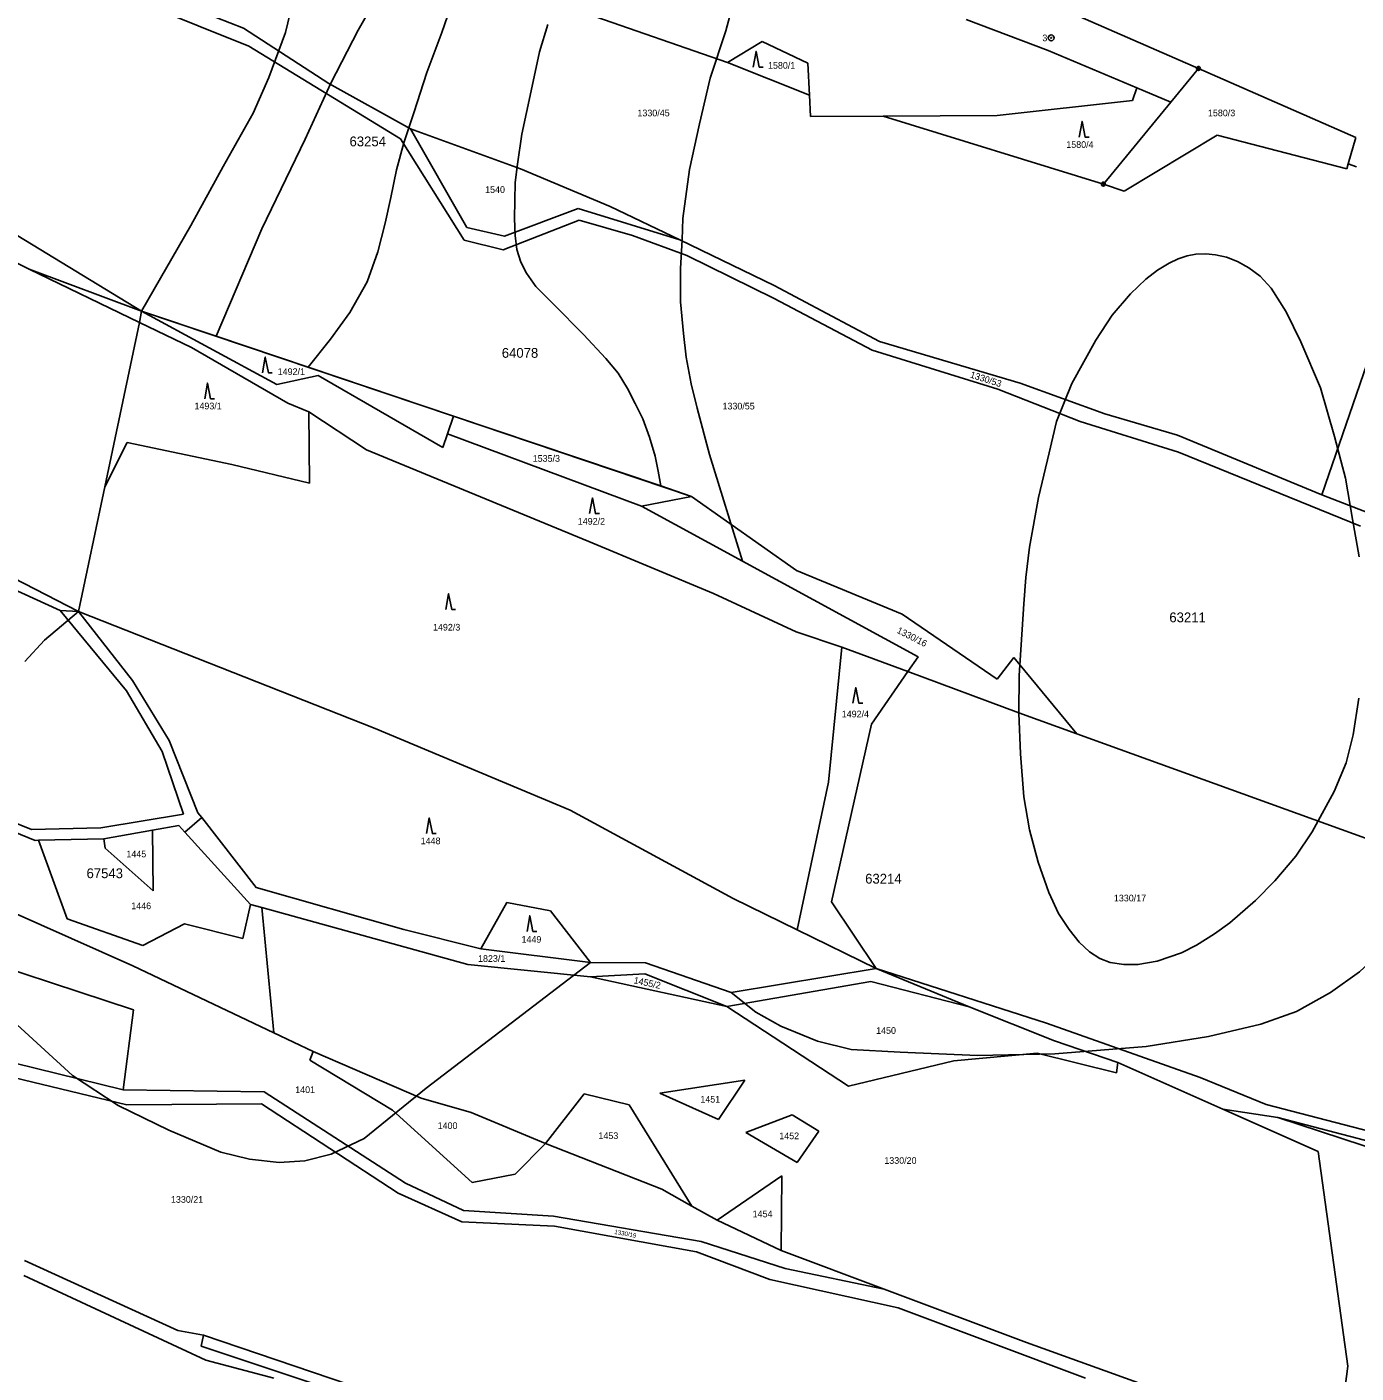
# Model space of a CAD drawing. Extents: x -546762 to -540209, y -1046851 to -1035694.
# Drawn here: x -542968.6 to -542629.5, y -1041335.5 to -1040992 of the extents above; entities that cross this region are included whole.
import ezdxf

# ---------------------------------------------------------------- set-up
doc = ezdxf.new("R2010")
doc.units = 0
for name, color, linetype in [('Vrstva 1', 7, 'Continuous'), ('Vrstva 17', 7, 'Continuous'), ('Vrstva 18', 7, 'Continuous'), ('Vrstva 24', 7, 'Continuous'), ('Vrstva 25', 7, 'Continuous'), ('Vrstva 52', 7, 'Continuous'), ('Vrstva 53', 7, 'Continuous'), ('Vrstva 6', 7, 'Continuous')]:
    doc.layers.add(name, color=color, linetype=linetype)

msp = doc.modelspace()

# ---------------------------------------------------------------- linework, layer by layer
at = {"layer": 'Vrstva 1'}
for points in [[(-542669.69, -1041002.63), (-542786.34, -1040951.58)], [(-542825.69, -1040988.7), (-542789.86, -1041001.15)], [(-542789.86, -1041001.15), (-542768.95, -1041009.45)], [(-542676.76, -1041011.23), (-542669.69, -1041002.63)], [(-542629.49, -1041020.22), (-542669.69, -1041002.63)], [(-542768.95, -1041009.45), (-542768.67, -1041014.93)], [(-542693.95, -1041032.14), (-542676.76, -1041011.23)], [(-542768.67, -1041014.93), (-542750.14, -1041014.82)], [(-542693.95, -1041032.14), (-542750.14, -1041014.82)], [(-542688.6, -1041033.92), (-542664.92, -1041019.69)], [(-542664.92, -1041019.69), (-542631.83, -1041028.25)], [(-542629.49, -1041020.22), (-542631.46, -1041026.99)], [(-542631.46, -1041026.99), (-542631.83, -1041028.25)], [(-542693.95, -1041032.14), (-542688.6, -1041033.92)], [(-542939.35, -1041064.58), (-542968.01, -1041053.85)], [(-542968.01, -1041053.85), (-542939.89, -1041067.45)], [(-542859.72, -1041091.39), (-542939.35, -1041064.58)], [(-542939.89, -1041067.45), (-542948.74, -1041109.37)], [(-542861.28, -1041095.86), (-542859.72, -1041091.39)], [(-542798.99, -1041111.82), (-542859.72, -1041091.39)], [(-542811.78, -1041114.34), (-542861.28, -1041095.86)], [(-542948.74, -1041109.37), (-542955.45, -1041141.18)], [(-542811.78, -1041114.34), (-542798.99, -1041111.82)], [(-542741.2, -1041152.77), (-542811.78, -1041114.34)], [(-542955.45, -1041141.18), (-542941.68, -1041158.79)], [(-542743.82, -1041156.54), (-542741.2, -1041152.77)], [(-542753.11, -1041169.93), (-542743.82, -1041156.54)], [(-542932.33, -1041174.09), (-542941.68, -1041158.79)], [(-542753.11, -1041169.93), (-542763.35, -1041215.27)], [(-542924.99, -1041192.52), (-542932.33, -1041174.09)], [(-542924.99, -1041192.52), (-542924, -1041193.79)], [(-542924, -1041193.79), (-542928.32, -1041197.49)], [(-542924, -1041193.79), (-542910.14, -1041211.61)], [(-542928.32, -1041197.49), (-542911.54, -1041215.94)], [(-542910.14, -1041211.61), (-542872.43, -1041222.33)], [(-542908.66, -1041216.74), (-542911.54, -1041215.94)], [(-542751.91, -1041232.29), (-542763.35, -1041215.27)], [(-542856.12, -1041231.25), (-542908.66, -1041216.74)], [(-542872.43, -1041222.33), (-542852.79, -1041227.26)], [(-542852.79, -1041227.26), (-542824.82, -1041230.74)], [(-542856.12, -1041231.25), (-542824.77, -1041234.42)], [(-542824.82, -1041230.74), (-542810.78, -1041230.84)], [(-542824.77, -1041234.42), (-542810.97, -1041233.64)], [(-542810.97, -1041233.64), (-542790.04, -1041241.95)], [(-542810.78, -1041230.84), (-542788.89, -1041238.38)], [(-542788.89, -1041238.38), (-542751.91, -1041232.29)], [(-542751.91, -1041232.29), (-542728.18, -1041242.08)], [(-542790.04, -1041241.95), (-542824.77, -1041234.42)], [(-542753.24, -1041235.61), (-542790.04, -1041241.95)], [(-542753.24, -1041235.61), (-542728.18, -1041242.08)]]:
    msp.add_lwpolyline(points, dxfattribs=at)
at = {"layer": 'Vrstva 24'}
for centre, radius in [((-542707.25, -1040994.84), 0.75), ((-542707.25, -1040994.84), 0.1), ((-542669.69, -1041002.63), 0.5), ((-542669.69, -1041002.63), 0.1), ((-542693.95, -1041032.14), 0.5), ((-542693.95, -1041032.14), 0.1)]:
    msp.add_circle(centre, radius, dxfattribs=at)
at = {"layer": 'Vrstva 25'}
for points in [[(-542783.26, -1041002.29), (-542782.56, -1040998.29), (-542781.76, -1041002.29), (-542780.76, -1041002.29)], [(-542700.09, -1041020.15), (-542699.39, -1041016.15), (-542698.59, -1041020.15), (-542697.59, -1041020.15)], [(-542908.49, -1041080.27), (-542907.79, -1041076.27), (-542906.99, -1041080.27), (-542905.99, -1041080.27)], [(-542923.22, -1041086.91), (-542922.52, -1041082.91), (-542921.72, -1041086.91), (-542920.72, -1041086.91)], [(-542825.03, -1041116.21), (-542824.33, -1041112.21), (-542823.53, -1041116.21), (-542822.53, -1041116.21)], [(-542861.72, -1041140.66), (-542861.02, -1041136.66), (-542860.22, -1041140.66), (-542859.22, -1041140.66)], [(-542757.83, -1041164.61), (-542757.13, -1041160.61), (-542756.33, -1041164.61), (-542755.33, -1041164.61)], [(-542866.65, -1041197.87), (-542865.95, -1041193.87), (-542865.15, -1041197.87), (-542864.15, -1041197.87)], [(-542840.98, -1041222.83), (-542840.28, -1041218.83), (-542839.48, -1041222.83), (-542838.48, -1041222.83)]]:
    msp.add_lwpolyline(points, dxfattribs=at)
at = {"layer": 'Vrstva 52'}
for points in [[(-542920.34, -1041070.98), (-542908.65, -1041043.54), (-542897.63, -1041020.64), (-542891.06, -1041006.43), (-542884.06, -1040992.86), (-542874.53, -1040976.11), (-542869.86, -1040965.72), (-542867.09, -1040958.26), (-542863.49, -1040946.59), (-542859.89, -1040933.45), (-542856.29, -1040921.99), (-542853.11, -1040913.94), (-542850.14, -1040907.58), (-542845.99, -1040901.52), (-542840.91, -1040895.34), (-542835.58, -1040889.88), (-542829.76, -1040884.43), (-542823.95, -1040879.71), (-542817.53, -1040875.71), (-542811.72, -1040873.16), (-542804.94, -1040871.59), (-542798.88, -1040870.86), (-542792.34, -1040870.98)], [(-542939.35, -1041064.58), (-542926.79, -1041042.67), (-542918.53, -1041027.62), (-542910.9, -1041014.05), (-542906.87, -1041004.93), (-542902.63, -1040993.48), (-542899.45, -1040980.33)], [(-542896.85, -1041078.89), (-542891.1, -1041071.73), (-542886.22, -1041064.94), (-542881.77, -1041057.1), (-542879.02, -1041049.46), (-542877.23, -1041042.07), (-542875.78, -1041035.52), (-542874.33, -1041028.49), (-542872.39, -1041021.59), (-542869.84, -1041013.95), (-542866.57, -1041003.65), (-542862.7, -1040993.48), (-542859.07, -1040982.81)], [(-542787.68, -1040983.46), (-542790.25, -1040993.01), (-542794.28, -1041005.1), (-542797.03, -1041016.76), (-542799.58, -1041028.42), (-542801.27, -1041040.93), (-542801.44, -1041046.4), (-542801.8, -1041053.67), (-542801.8, -1041062.16), (-542801.08, -1041070.28), (-542800.35, -1041076.33), (-542799.14, -1041083.12), (-542797.57, -1041089.3), (-542794.42, -1041101.17), (-542786.05, -1041128.35)], [(-542835.66, -1040991.42), (-542837.81, -1040998.42), (-542839.95, -1041008.32), (-542842.31, -1041019.4), (-542843.41, -1041027.08), (-542844.04, -1041031.72), (-542844.17, -1041040.93), (-542844.04, -1041045.22), (-542843.57, -1041048.85), (-542842.6, -1041052.03), (-542841.15, -1041054.87), (-542838.73, -1041058.26), (-542834.16, -1041062.9), (-542826.55, -1041070.52), (-542820.87, -1041076.61), (-542817.76, -1041080.42), (-542815.34, -1041084.3), (-542813.38, -1041088.09), (-542811.44, -1041092.03), (-542809.78, -1041096.67), (-542808.26, -1041101.52), (-542807.56, -1041105.4), (-542806.89, -1041109.16)], [(-543046.13, -1041004.38), (-543041.77, -1041005.42), (-543036.64, -1041007.64), (-543023.7, -1041013.66), (-543011.94, -1041020.45), (-542939.35, -1041064.58)], [(-542628.77, -1041163.32), (-542630.22, -1041172.65), (-542632.04, -1041179.8), (-542635.1, -1041187.1), (-542640.64, -1041197.42), (-542644.86, -1041203.58), (-542650.19, -1041209.95), (-542655.17, -1041214.94), (-542661.67, -1041220.61), (-542665.62, -1041223.45), (-542670.19, -1041226.29), (-542673.99, -1041228.3), (-542680.22, -1041230.45), (-542685.13, -1041231.28), (-542688.73, -1041231.28), (-542692.19, -1041230.72), (-542694.82, -1041229.75), (-542697.45, -1041228.02), (-542700.15, -1041225.53), (-542702.71, -1041222.34), (-542705.36, -1041218.26), (-542707.9, -1041212.93), (-542710.57, -1041205.17), (-542712.75, -1041196.93), (-542714.2, -1041188.45), (-542715.05, -1041177.54), (-542715.53, -1041167.12), (-542715.41, -1041157.55), (-542714.2, -1041139.25), (-542713.73, -1041132.49), (-542712.76, -1041124.74), (-542710.46, -1041112.14), (-542707.79, -1041100.75), (-542705.88, -1041092.71), (-542702.01, -1041083.02), (-542695.91, -1041071.99), (-542691.72, -1041065.58), (-542687.01, -1041060.16), (-542683.11, -1041056.39), (-542680.1, -1041054.06), (-542677.13, -1041052.28), (-542674.88, -1041051.25), (-542672.59, -1041050.46), (-542670.37, -1041049.98)], [(-542670.37, -1041049.98), (-542667.76, -1041049.94), (-542665.31, -1041050.18)], [(-542665.31, -1041050.18), (-542662.5, -1041050.77), (-542659.73, -1041051.88), (-542656.85, -1041053.54), (-542653.96, -1041055.6), (-542651.17, -1041058.71), (-542647.29, -1041064.77), (-542643.54, -1041072.41), (-542638.57, -1041084.16), (-542634.95, -1041096.55), (-542632.16, -1041107.21), (-542630.35, -1041117.63), (-542628.65, -1041127.21)], [(-542955.45, -1041141.18), (-542948.74, -1041109.37), (-542939.89, -1041067.45), (-542939.35, -1041064.58)], [(-542939.35, -1041064.58), (-542920.34, -1041070.98)], [(-542920.34, -1041070.98), (-542896.85, -1041078.89)], [(-542896.85, -1041078.89), (-542859.72, -1041091.39), (-542806.89, -1041109.16)], [(-542806.89, -1041109.16), (-542798.99, -1041111.82), (-542811.78, -1041114.34), (-542786.05, -1041128.35)], [(-542786.05, -1041128.35), (-542741.2, -1041152.77), (-542743.82, -1041156.54), (-542753.11, -1041169.93), (-542763.35, -1041215.27), (-542751.91, -1041232.29), (-542788.89, -1041238.38)], [(-542969.1, -1041153.99), (-542964.14, -1041148.54), (-542955.45, -1041141.18)], [(-542955.45, -1041141.18), (-542941.68, -1041158.79)], [(-542941.68, -1041158.79), (-542932.33, -1041174.09), (-542924.99, -1041192.52), (-542924, -1041193.79), (-542910.14, -1041211.61), (-542872.43, -1041222.33), (-542852.79, -1041227.26), (-542824.82, -1041230.74)], [(-542788.89, -1041238.38), (-542782.63, -1041243.39), (-542776.22, -1041247.02), (-542766.89, -1041250.78), (-542758.29, -1041252.96), (-542745.79, -1041253.66), (-542726.08, -1041254.5), (-542706.37, -1041254.08), (-542683.05, -1041252.17), (-542667.16, -1041249.63), (-542653.81, -1041246.45), (-542644.69, -1041243.26), (-542636, -1041238.39), (-542628.59, -1041233.09), (-542620.74, -1041225.88), (-542615.37, -1041218.81), (-542605.62, -1041201.21)], [(-542824.82, -1041230.74), (-542866.71, -1041262.8), (-542882.57, -1041275.65), (-542890.93, -1041279.65), (-542897.71, -1041281.34), (-542904.25, -1041281.77), (-542911.76, -1041280.92), (-542919.15, -1041279.1), (-542932.35, -1041273.53), (-542945.31, -1041267.23), (-542956.93, -1041259.59), (-542974.13, -1041243.84)], [(-542788.89, -1041238.38), (-542810.78, -1041230.84), (-542824.82, -1041230.74)]]:
    msp.add_lwpolyline(points, dxfattribs=at)
at = {"layer": 'Vrstva 6'}
for points in [[(-542962.12, -1040973.22), (-542913.3, -1040992.35)], [(-542963.29, -1040976.25), (-542911.96, -1040996.99)], [(-542913.3, -1040992.35), (-542891.53, -1041006.49)], [(-542708.03, -1040998.09), (-542728.96, -1040990.15)], [(-542781, -1040995.72), (-542789.86, -1041001.15)], [(-542769.37, -1041001.31), (-542781, -1040995.72)], [(-542911.96, -1040996.99), (-542873.27, -1041020.63)], [(-542685.4, -1041007.6), (-542708.03, -1040998.09)], [(-542768.95, -1041009.45), (-542769.37, -1041001.31)], [(-542891.53, -1041006.49), (-542870.7, -1041018.06)], [(-542686.51, -1041010.8), (-542685.4, -1041007.6)], [(-542676.76, -1041011.23), (-542685.4, -1041007.6)], [(-542721.02, -1041014.65), (-542686.51, -1041010.8)], [(-542750.14, -1041014.82), (-542721.02, -1041014.65)], [(-542873.27, -1041020.63), (-542857.04, -1041046.49)], [(-542870.7, -1041018.06), (-542842.69, -1041028.25)], [(-542856.36, -1041043.2), (-542870.7, -1041018.06)], [(-542631.46, -1041026.99), (-542629.39, -1041027.77)], [(-542842.69, -1041028.25), (-542819.75, -1041037.82)], [(-542638.23, -1041111.45), (-542611.71, -1041034.4)], [(-542968.01, -1041053.85), (-543006.53, -1041034.56)], [(-542819.75, -1041037.82), (-542801.98, -1041046.4)], [(-542847.04, -1041048.92), (-542827.72, -1041041.33)], [(-542846.72, -1041045.45), (-542827.96, -1041038.38)], [(-542827.96, -1041038.38), (-542801.98, -1041046.4)], [(-542827.72, -1041041.33), (-542814.08, -1041045.23)], [(-542856.36, -1041043.2), (-542846.72, -1041045.45)], [(-542857.04, -1041046.49), (-542847.04, -1041048.92)], [(-542814.08, -1041045.23), (-542800.19, -1041050.39)], [(-542801.98, -1041046.4), (-542777.97, -1041058)], [(-542800.19, -1041050.39), (-542777.96, -1041061.32)], [(-542777.97, -1041058), (-542751.07, -1041072.3)], [(-542777.96, -1041061.32), (-542752.92, -1041074.51)], [(-542904.79, -1041083.3), (-542939.35, -1041064.58)], [(-542939.89, -1041067.45), (-542926.62, -1041073.87)], [(-542751.07, -1041072.3), (-542715.17, -1041082.9)], [(-542926.62, -1041073.87), (-542902.06, -1041088.06)], [(-542752.92, -1041074.51), (-542720.9, -1041084.45)], [(-542894.24, -1041080.96), (-542904.79, -1041083.3)], [(-542862.49, -1041099.32), (-542894.24, -1041080.96)], [(-542720.9, -1041084.45), (-542699.9, -1041092.71)], [(-542715.17, -1041082.9), (-542693.54, -1041090.8)], [(-542902.06, -1041088.06), (-542896.69, -1041090.28)], [(-542896.5, -1041108.47), (-542896.69, -1041090.28)], [(-542896.69, -1041090.28), (-542881.91, -1041099.92)], [(-542699.9, -1041092.71), (-542674.77, -1041100.51)], [(-542693.54, -1041090.8), (-542675.04, -1041096.2)], [(-542861.28, -1041095.86), (-542862.49, -1041099.32)], [(-542675.04, -1041096.2), (-542638.23, -1041111.45)], [(-542948.74, -1041109.37), (-542943.05, -1041098.05)], [(-542943.05, -1041098.05), (-542916.32, -1041103.69)], [(-542881.91, -1041099.92), (-542825.25, -1041123.35)], [(-542674.77, -1041100.51), (-542628.37, -1041119.45)], [(-542916.32, -1041103.69), (-542896.5, -1041108.47)], [(-543023.47, -1041112.01), (-542960.13, -1041140.93)], [(-542798.99, -1041111.82), (-542772.23, -1041130.77)], [(-542638.23, -1041111.45), (-542545.5, -1041147.28)], [(-542825.25, -1041123.35), (-542793.41, -1041136.64)], [(-542980.42, -1041128.34), (-542955.45, -1041141.18)], [(-542772.23, -1041130.77), (-542745.27, -1041141.86)], [(-542772.36, -1041146.4), (-542793.41, -1041136.64)], [(-542955.45, -1041141.18), (-542960.13, -1041140.93)], [(-542960.13, -1041140.93), (-542943.22, -1041161.44)], [(-542955.45, -1041141.18), (-542879.75, -1041171.07)], [(-542745.27, -1041141.86), (-542721.07, -1041158.46)], [(-542760.71, -1041150.26), (-542772.36, -1041146.4)], [(-542760.71, -1041150.26), (-542764.09, -1041184.74)], [(-542743.82, -1041156.54), (-542760.71, -1041150.26)], [(-542716.81, -1041152.94), (-542721.07, -1041158.46)], [(-542700.7, -1041172.43), (-542716.81, -1041152.94)], [(-542715.53, -1041167.07), (-542743.82, -1041156.54)], [(-542943.22, -1041161.44), (-542934.1, -1041176.87)], [(-542700.7, -1041172.43), (-542715.53, -1041167.07)], [(-542967.46, -1041196.84), (-543032.07, -1041170.61)], [(-542879.75, -1041171.07), (-542829.99, -1041191.92)], [(-542597.92, -1041209.59), (-542700.7, -1041172.43)], [(-542934.1, -1041176.87), (-542928.61, -1041192.88)], [(-542764.09, -1041184.74), (-542772.06, -1041222.43)], [(-542984.39, -1041192.33), (-542966.48, -1041199.59)], [(-542788.43, -1041214.43), (-542829.99, -1041191.92)], [(-542928.61, -1041192.88), (-542949.73, -1041196.39)], [(-542929.83, -1041195.83), (-542936.54, -1041197.01)], [(-542929.83, -1041195.83), (-542928.32, -1041197.49)], [(-542949.73, -1041196.39), (-542967.46, -1041196.84)], [(-542948.93, -1041199.19), (-542965.65, -1041199.57)], [(-542936.54, -1041197.01), (-542948.93, -1041199.19)], [(-542948.93, -1041199.19), (-542948.64, -1041201.55)], [(-542936.54, -1041197.01), (-542936.39, -1041212.47)], [(-542965.65, -1041199.57), (-542966.48, -1041199.59)], [(-542958.35, -1041219.58), (-542965.65, -1041199.57)], [(-542948.64, -1041201.55), (-542936.39, -1041212.47)], [(-543004.26, -1041203.7), (-542941.53, -1041231.62)], [(-542913.47, -1041224.64), (-542911.54, -1041215.94)], [(-542852.79, -1041227.26), (-542846.17, -1041215.48)], [(-542846.17, -1041215.48), (-542835.02, -1041217.54)], [(-542772.06, -1041222.43), (-542788.43, -1041214.43)], [(-542958.35, -1041219.58), (-542939, -1041226.41)], [(-542908.66, -1041216.74), (-542905.57, -1041248.68)], [(-542824.82, -1041230.74), (-542835.02, -1041217.54)], [(-542939, -1041226.41), (-542928.41, -1041220.91)], [(-542928.41, -1041220.91), (-542913.47, -1041224.64)], [(-542751.91, -1041232.29), (-542772.06, -1041222.43)], [(-542990.54, -1041226.66), (-542941.37, -1041242.79)], [(-542941.53, -1041231.62), (-542905.57, -1041248.68)], [(-542751.91, -1041232.29), (-542708.48, -1041246.19)], [(-542941.37, -1041242.79), (-542944.06, -1041263.27)], [(-542790.04, -1041241.95), (-542758.96, -1041262.32)], [(-542728.18, -1041242.08), (-542706.45, -1041250.73)], [(-542708.48, -1041246.19), (-542669.27, -1041260.1)], [(-542905.57, -1041248.68), (-542895.53, -1041253.44)], [(-542706.45, -1041250.73), (-542690.27, -1041256.22)], [(-542896.37, -1041255.68), (-542895.53, -1041253.44)], [(-542895.53, -1041253.44), (-542868.04, -1041265.33)], [(-542732.13, -1041255.86), (-542710.87, -1041253.85)], [(-542710.87, -1041253.85), (-542690.58, -1041258.86)], [(-542944.06, -1041263.27), (-542972.05, -1041256.33)], [(-542896.37, -1041255.68), (-542875.32, -1041268.43)], [(-542758.96, -1041262.32), (-542732.13, -1041255.86)], [(-542690.58, -1041258.86), (-542690.27, -1041256.22)], [(-542690.27, -1041256.22), (-542663.44, -1041268.15)], [(-542943.07, -1041267.09), (-542971.98, -1041260.06)], [(-542807.15, -1041264.07), (-542785.4, -1041260.78)], [(-542785.4, -1041260.78), (-542792.11, -1041270.79)], [(-542669.27, -1041260.1), (-542652.37, -1041266.96)], [(-542944.06, -1041263.27), (-542908.02, -1041263.77)], [(-542908.02, -1041263.77), (-542872.01, -1041287.03)], [(-542836.32, -1041276.9), (-542826.43, -1041264.29)], [(-542826.43, -1041264.29), (-542814.97, -1041267.08)], [(-542792.11, -1041270.79), (-542807.15, -1041264.07)], [(-542943.07, -1041267.09), (-542908.76, -1041266.81)], [(-542908.76, -1041266.81), (-542873.88, -1041289.64)], [(-542868.04, -1041265.33), (-542855.24, -1041269)], [(-542814.97, -1041267.08), (-542798.91, -1041292.91)], [(-542652.37, -1041266.96), (-542619.33, -1041275.58)], [(-542875.32, -1041268.43), (-542854.99, -1041286.85)], [(-542855.24, -1041269), (-542836.32, -1041276.9)], [(-542773.38, -1041269.65), (-542785.2, -1041274.15)], [(-542766.53, -1041273.74), (-542773.38, -1041269.65)], [(-542649.4, -1041270.33), (-542663.44, -1041268.15)], [(-542663.44, -1041268.15), (-542639.16, -1041278.94)], [(-542620.19, -1041277.98), (-542649.4, -1041270.33)], [(-542649.4, -1041270.33), (-542611.32, -1041282.81)], [(-542785.2, -1041274.15), (-542772.11, -1041281.8)], [(-542772.11, -1041281.8), (-542766.53, -1041273.74)], [(-542844.05, -1041284.74), (-542836.32, -1041276.9)], [(-542836.32, -1041276.9), (-542806.62, -1041288.6)], [(-542631.54, -1041333.76), (-542639.16, -1041278.94)], [(-542854.99, -1041286.85), (-542844.05, -1041284.74)], [(-542775.94, -1041285.14), (-542792.46, -1041296.51)], [(-542775.94, -1041285.14), (-542776.19, -1041304.21)], [(-542872.01, -1041287.03), (-542857.16, -1041293.99)], [(-542806.62, -1041288.6), (-542798.91, -1041292.91)], [(-542873.88, -1041289.64), (-542857.63, -1041296.93)], [(-542857.16, -1041293.99), (-542834.21, -1041295.46)], [(-542834.21, -1041295.46), (-542796.55, -1041301.94)], [(-542798.91, -1041292.91), (-542792.46, -1041296.51)], [(-542857.63, -1041296.93), (-542834.01, -1041298)], [(-542834.01, -1041298), (-542797.76, -1041304.55)], [(-542792.46, -1041296.51), (-542776.19, -1041304.21)], [(-542796.55, -1041301.94), (-542775.14, -1041308.82)], [(-542797.76, -1041304.55), (-542779.07, -1041311.63)], [(-542776.19, -1041304.21), (-542749.86, -1041314.1)], [(-542930.11, -1041324.67), (-542969.17, -1041306.79)], [(-542775.14, -1041308.82), (-542749.86, -1041314.1)], [(-542922.96, -1041332.17), (-542969.38, -1041310.64)], [(-542779.07, -1041311.63), (-542746.32, -1041318.89)], [(-542749.86, -1041314.1), (-542713.57, -1041327.73)], [(-542698.51, -1041336.81), (-542746.32, -1041318.89)], [(-542930.11, -1041324.67), (-542923.56, -1041325.82)], [(-542924.12, -1041328.6), (-542923.56, -1041325.82)], [(-542923.56, -1041325.82), (-542877.15, -1041341.54)], [(-542924.12, -1041328.6), (-542877.7, -1041344.13)], [(-542634.49, -1041356.2), (-542713.57, -1041327.73)], [(-542922.96, -1041332.17), (-542905.61, -1041336.79)], [(-542631.54, -1041333.76), (-542634.49, -1041356.2)]]:
    msp.add_lwpolyline(points, dxfattribs=at)

# ---------------------------------------------------------------- texts
at = {"layer": 'Vrstva 17'}
msp.add_text('3', height=1.7, dxfattribs=at).set_placement((-542709.51, -1040995.69))
at = {"layer": 'Vrstva 18'}
for s, p in [('1580/1', (-542779.51, -1041002.71)), ('1330/45', (-542812.82, -1041014.85)), ('1580/3', (-542667.26, -1041014.83)), ('1580/4', (-542703.4, -1041022.9)), ('1540', (-542851.68, -1041034.39)), ('1492/1', (-542904.61, -1041080.84)), ('1493/1', (-542925.84, -1041089.61)), ('1330/55', (-542791.12, -1041089.64)), ('1535/3', (-542839.54, -1041102.99)), ('1492/2', (-542828.04, -1041119.03)), ('1492/3', (-542864.98, -1041146.05)), ('1492/4', (-542760.69, -1041168.2)), ('1448', (-542868.12, -1041200.57)), ('1445', (-542943.21, -1041203.92)), ('1446', (-542941.96, -1041217.14)), ('1330/17', (-542691.26, -1041215.16)), ('1449', (-542842.4, -1041225.7)), ('1823/1', (-542853.49, -1041230.58)), ('1450', (-542751.92, -1041248.95)), ('1401', (-542900.14, -1041264.05)), ('1451', (-542796.77, -1041266.49)), ('1400', (-542863.79, -1041273.22)), ('1453', (-542822.77, -1041275.79)), ('1452', (-542776.63, -1041275.83)), ('1330/20', (-542749.83, -1041282.12)), ('1330/21', (-542931.84, -1041292.06)), ('1454', (-542783.43, -1041295.74))]:
    msp.add_text(s, height=1.7, dxfattribs=at).set_placement(p)
for s, height, rotation, p in [('1330/53', 1.7, 342.2485, (-542728.08, -1041081.47)), ('1330/16', 1.7, 332.9552, (-542746.8, -1041146.55)), ('1455/2', 1.7, 347.9995, (-542813.89, -1041236.04)), ('1330/19', 1.14, 349.4939, (-542818.8, -1041299.98))]:
    msp.add_text(s, height=height, rotation=rotation, dxfattribs=at).set_placement(p)
at = {"layer": 'Vrstva 53'}
for s, p in [('63254', (-542886.28, -1041022.5)), ('64078', (-542847.43, -1041076.46)), ('63211', (-542677.11, -1041143.94)), ('67543', (-542953.38, -1041209.23)), ('63214', (-542754.72, -1041210.62))]:
    msp.add_text(s, height=2.5, dxfattribs=at).set_placement(p)

doc.saveas('drawing.dxf')
